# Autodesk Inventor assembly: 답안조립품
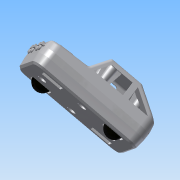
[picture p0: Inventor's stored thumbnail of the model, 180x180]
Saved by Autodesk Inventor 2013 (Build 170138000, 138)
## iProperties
Created: 2015-05
Part Number: 답안조립품
Document SubType Name: Assembly
Designer: Administrator
Author: Administrator
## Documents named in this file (5)
- C:\Documents and Settings\Administrator\바탕 화면\450507V1010\답안조립품.iam
- C:\Documents and Settings\Administrator\바탕 화면\450507V1010\1-본체.ipt
- C:\Documents and Settings\Administrator\바탕 화면\450507V1010\커버.ipt
- C:\Documents and Settings\Administrator\바탕 화면\450507V1010\바퀴고정부.ipt
- C:\Documents and Settings\Administrator\바탕 화면\450507V1010\바퀴.ipt
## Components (1 placed, 1 different names)
1. 1-본체:1
